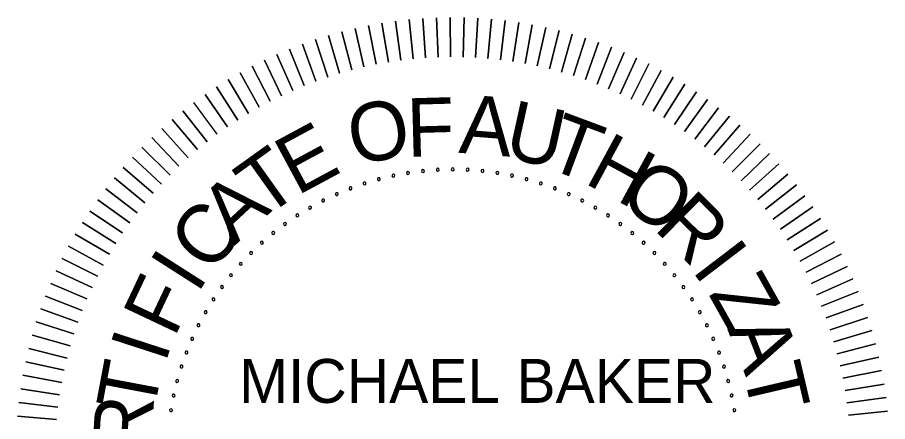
# Model space of a CAD drawing. Extents: x -0.54 to 1.64, y 0 to 0.92.
# Drawn here: x 1.1174 to 1.2012, y 0.1133 to 0.1521 of the extents above; entities that cross this region are included whole.
import ezdxf

# ---------------------------------------------------------------- set-up
doc = ezdxf.new("R2010")
doc.units = 0
doc.layers.add('STAMP_COA', color=7, linetype='Continuous')

msp = doc.modelspace()

# ---------------------------------------------------------------- linework, layer by layer
at = {"layer": 'STAMP_COA'}
for points in [[(1.153107, 0.147847), (1.152493, 0.15159)], [(1.152493, 0.15159), (1.153107, 0.147847)], [(1.154296, 0.148023), (1.1538, 0.151784)], [(1.1538, 0.151784), (1.154296, 0.148023)], [(1.155491, 0.148162), (1.155113, 0.151936)], [(1.155113, 0.151936), (1.155491, 0.148162)], [(1.156688, 0.148263), (1.156429, 0.152047)], [(1.156429, 0.152047), (1.156688, 0.148263)], [(1.157889, 0.148326), (1.157749, 0.152117)], [(1.157749, 0.152117), (1.157889, 0.148326)], [(1.159091, 0.148352), (1.15907, 0.152145)], [(1.15907, 0.152145), (1.159091, 0.148352)], [(1.160293, 0.148339), (1.160391, 0.152131)], [(1.160391, 0.152131), (1.160293, 0.148339)], [(1.161494, 0.14829), (1.161711, 0.152076)], [(1.161711, 0.152076), (1.161494, 0.14829)], [(1.162693, 0.148202), (1.163029, 0.15198)], [(1.163029, 0.15198), (1.162693, 0.148202)], [(1.163888, 0.148077), (1.164343, 0.151842)], [(1.164343, 0.151842), (1.163888, 0.148077)], [(1.16508, 0.147914), (1.165652, 0.151664)], [(1.165652, 0.151664), (1.16508, 0.147914)], [(1.149581, 0.147096), (1.148617, 0.150765)], [(1.148617, 0.150765), (1.149581, 0.147096)], [(1.150748, 0.147384), (1.1499, 0.151081)], [(1.1499, 0.151081), (1.150748, 0.147384)], [(1.151924, 0.147634), (1.151193, 0.151356)], [(1.151193, 0.151356), (1.151924, 0.147634)], [(1.166265, 0.147714), (1.166955, 0.151444)], [(1.166955, 0.151444), (1.166265, 0.147714)], [(1.167443, 0.147477), (1.16825, 0.151183)], [(1.16825, 0.151183), (1.167443, 0.147477)], [(1.168614, 0.147202), (1.169537, 0.150882)], [(1.169537, 0.150882), (1.168614, 0.147202)], [(1.147276, 0.146413), (1.146084, 0.150014)], [(1.146084, 0.150014), (1.147276, 0.146413)], [(1.148423, 0.146773), (1.147345, 0.150409)], [(1.147345, 0.150409), (1.148423, 0.146773)], [(1.169775, 0.146892), (1.170813, 0.15054)], [(1.170813, 0.15054), (1.169775, 0.146892)], [(1.170926, 0.146545), (1.172078, 0.150159)], [(1.172078, 0.150159), (1.170926, 0.146545)], [(1.145019, 0.145586), (1.143603, 0.149105)], [(1.143603, 0.149105), (1.145019, 0.145586)], [(1.146141, 0.146017), (1.144836, 0.149579)], [(1.144836, 0.149579), (1.146141, 0.146017)], [(1.172066, 0.146162), (1.173331, 0.149738)], [(1.173331, 0.149738), (1.172066, 0.146162)], [(1.173192, 0.145743), (1.174569, 0.149277)], [(1.174569, 0.149277), (1.173192, 0.145743)], [(1.143911, 0.14512), (1.142385, 0.148592)], [(1.142385, 0.148592), (1.143911, 0.14512)], [(1.174306, 0.145289), (1.175793, 0.148779)], [(1.175793, 0.148779), (1.174306, 0.145289)], [(1.175404, 0.144801), (1.177, 0.148242)], [(1.177, 0.148242), (1.175404, 0.144801)], [(1.141742, 0.144084), (1.140001, 0.147454)], [(1.140001, 0.147454), (1.141742, 0.144084)], [(1.142818, 0.144619), (1.141184, 0.148042)], [(1.141184, 0.148042), (1.142818, 0.144619)], [(1.176486, 0.144278), (1.17819, 0.147667)], [(1.17819, 0.147667), (1.176486, 0.144278)], [(1.140682, 0.143516), (1.138837, 0.146829)], [(1.138837, 0.146829), (1.140682, 0.143516)], [(1.177552, 0.143721), (1.179361, 0.147055)], [(1.179361, 0.147055), (1.177552, 0.143721)], [(1.139641, 0.142914), (1.137692, 0.146168)], [(1.137692, 0.146168), (1.139641, 0.142914)], [(1.1786, 0.143131), (1.180512, 0.146407)], [(1.180512, 0.146407), (1.1786, 0.143131)], [(1.179628, 0.142509), (1.181643, 0.145723)], [(1.181643, 0.145723), (1.179628, 0.142509)], [(1.13862, 0.14228), (1.13657, 0.145472)], [(1.13657, 0.145472), (1.13862, 0.14228)], [(1.180636, 0.141855), (1.182751, 0.145004)], [(1.182751, 0.145004), (1.180636, 0.141855)], [(1.137619, 0.141615), (1.135469, 0.14474)], [(1.135469, 0.14474), (1.137619, 0.141615)], [(1.181624, 0.141169), (1.183836, 0.14425)], [(1.183836, 0.14425), (1.181624, 0.141169)], [(1.136639, 0.140918), (1.134393, 0.143974)], [(1.182589, 0.140452), (1.184897, 0.143462)], [(1.184897, 0.143462), (1.182589, 0.140452)], [(1.135682, 0.140191), (1.133341, 0.143175)], [(1.133341, 0.143175), (1.135682, 0.140191)], [(1.183531, 0.139706), (1.185933, 0.142642)], [(1.185933, 0.142642), (1.183531, 0.139706)], [(1.134748, 0.139434), (1.132314, 0.142343)], [(1.132314, 0.142343), (1.134748, 0.139434)], [(1.18445, 0.13893), (1.186942, 0.14179)], [(1.186942, 0.14179), (1.18445, 0.13893)], [(1.133838, 0.138648), (1.131314, 0.14148)], [(1.131314, 0.14148), (1.133838, 0.138648)], [(1.187925, 0.140906), (1.185344, 0.138126)], [(1.185344, 0.138126), (1.187925, 0.140906)], [(1.132954, 0.137834), (1.130342, 0.140585)], [(1.130342, 0.140585), (1.132954, 0.137834)], [(1.188879, 0.139992), (1.186211, 0.137295)], [(1.186211, 0.137295), (1.188879, 0.139992)], [(1.132095, 0.136993), (1.129398, 0.13966)], [(1.129398, 0.13966), (1.132095, 0.136993)], [(1.189803, 0.139048), (1.187053, 0.136436)], [(1.187053, 0.136436), (1.189803, 0.139048)], [(1.131263, 0.136125), (1.128484, 0.138706)], [(1.128484, 0.138706), (1.131263, 0.136125)], [(1.130459, 0.135231), (1.1276, 0.137724)], [(1.1276, 0.137724), (1.130459, 0.135231)], [(1.190698, 0.138076), (1.187867, 0.135551)], [(1.187867, 0.135551), (1.190698, 0.138076)], [(1.129684, 0.134313), (1.126748, 0.136714)], [(1.126748, 0.136714), (1.129684, 0.134313)], [(1.191562, 0.137076), (1.188653, 0.134642)], [(1.188653, 0.134642), (1.191562, 0.137076)], [(1.128937, 0.133371), (1.125927, 0.135679)], [(1.125927, 0.135679), (1.128937, 0.133371)], [(1.192394, 0.136049), (1.189409, 0.133708)], [(1.189409, 0.133708), (1.192394, 0.136049)], [(1.193193, 0.134997), (1.190137, 0.13275)], [(1.190137, 0.13275), (1.193193, 0.134997)], [(1.128221, 0.132405), (1.12514, 0.134618)], [(1.12514, 0.134618), (1.128221, 0.132405)], [(1.127535, 0.131418), (1.124386, 0.133532)], [(1.124386, 0.133532), (1.127535, 0.131418)], [(1.193959, 0.13392), (1.190833, 0.131771)], [(1.190833, 0.131771), (1.193959, 0.13392)], [(1.126881, 0.130409), (1.123667, 0.132424)], [(1.123667, 0.132424), (1.126881, 0.130409)], [(1.19469, 0.13282), (1.191499, 0.13077)], [(1.191499, 0.13077), (1.19469, 0.13282)], [(1.195387, 0.131697), (1.192133, 0.129748)], [(1.192133, 0.129748), (1.195387, 0.131697)], [(1.126258, 0.129381), (1.122983, 0.131294)], [(1.122983, 0.131294), (1.126258, 0.129381)], [(1.125668, 0.128334), (1.122334, 0.130142)], [(1.122334, 0.130142), (1.125668, 0.128334)], [(1.196048, 0.130553), (1.192734, 0.128707)], [(1.192734, 0.128707), (1.196048, 0.130553)], [(1.125112, 0.127268), (1.121723, 0.128971)], [(1.121723, 0.128971), (1.125112, 0.127268)], [(1.196673, 0.129389), (1.193303, 0.127648)], [(1.193303, 0.127648), (1.196673, 0.129389)], [(1.19726, 0.128206), (1.193837, 0.126571)], [(1.193837, 0.126571), (1.19726, 0.128206)], [(1.124589, 0.126186), (1.121148, 0.127781)], [(1.121148, 0.127781), (1.124589, 0.126186)], [(1.1241, 0.125087), (1.120611, 0.126574)], [(1.120611, 0.126574), (1.1241, 0.125087)], [(1.197811, 0.127004), (1.194338, 0.125479)], [(1.194338, 0.125479), (1.197811, 0.127004)], [(1.198323, 0.125786), (1.194804, 0.124371)], [(1.194804, 0.124371), (1.198323, 0.125786)], [(1.123647, 0.123974), (1.120112, 0.125351)], [(1.120112, 0.125351), (1.123647, 0.123974)], [(1.123228, 0.122847), (1.119652, 0.124112)], [(1.119652, 0.124112), (1.123228, 0.122847)], [(1.198797, 0.124553), (1.195236, 0.123248)], [(1.195236, 0.123248), (1.198797, 0.124553)], [(1.199232, 0.123305), (1.195631, 0.122113)], [(1.195631, 0.122113), (1.199232, 0.123305)], [(1.122845, 0.121708), (1.119231, 0.12286)], [(1.119231, 0.12286), (1.122845, 0.121708)], [(1.122498, 0.120557), (1.11885, 0.121595)], [(1.11885, 0.121595), (1.122498, 0.120557)], [(1.199628, 0.122045), (1.195991, 0.120966)], [(1.195991, 0.120966), (1.199628, 0.122045)], [(1.199984, 0.120772), (1.196315, 0.119809)], [(1.196315, 0.119809), (1.199984, 0.120772)], [(1.122187, 0.119395), (1.118508, 0.120318)], [(1.118508, 0.120318), (1.122187, 0.119395)], [(1.121913, 0.118225), (1.118207, 0.119032)], [(1.118207, 0.119032), (1.121913, 0.118225)], [(1.200299, 0.119489), (1.196602, 0.118641)], [(1.196602, 0.118641), (1.200299, 0.119489)], [(1.200574, 0.118197), (1.196852, 0.117465)], [(1.196852, 0.117465), (1.200574, 0.118197)], [(1.121676, 0.117046), (1.117946, 0.117736)], [(1.117946, 0.117736), (1.121676, 0.117046)], [(1.121476, 0.115861), (1.117726, 0.116434)], [(1.117726, 0.116434), (1.121476, 0.115861)], [(1.200809, 0.116897), (1.197066, 0.116282)], [(1.197066, 0.116282), (1.200809, 0.116897)], [(1.201002, 0.11559), (1.197242, 0.115093)], [(1.197242, 0.115093), (1.201002, 0.11559)], [(1.121313, 0.11467), (1.117547, 0.115124)], [(1.117547, 0.115124), (1.121313, 0.11467)], [(1.201154, 0.114277), (1.19738, 0.113899)], [(1.19738, 0.113899), (1.201154, 0.114277)], [(1.121188, 0.113474), (1.11741, 0.11381)], [(1.11741, 0.11381), (1.121188, 0.113474)]]:
    msp.add_lwpolyline(points, dxfattribs=at)
for centre, start, end in [((1.156435, 0.137385), 6, 186), ((1.156435, 0.137385), 186, 6), ((1.157867, 0.137498), 3, 183), ((1.157867, 0.137498), 183, 3), ((1.159304, 0.137535), 0, 180), ((1.159304, 0.137535), 180, 0), ((1.160741, 0.137498), 357, 177), ((1.160741, 0.137498), 177, 357), ((1.162173, 0.137385), 174, 354), ((1.162173, 0.137385), 354, 174), ((1.1522, 0.1366), 15, 195), ((1.1522, 0.1366), 195, 15), ((1.153597, 0.136935), 12, 192), ((1.153597, 0.136935), 192, 12), ((1.15501, 0.137197), 9, 189), ((1.15501, 0.137197), 189, 9), ((1.163598, 0.137197), 171, 351), ((1.163598, 0.137197), 351, 171), ((1.165011, 0.136935), 168, 348), ((1.165011, 0.136935), 348, 168), ((1.166409, 0.1366), 165, 345), ((1.166409, 0.1366), 345, 165), ((1.149467, 0.135712), 21, 201), ((1.149467, 0.135712), 201, 21), ((1.150822, 0.136192), 18, 198), ((1.150822, 0.136192), 198, 18), ((1.167786, 0.136192), 162, 342), ((1.167786, 0.136192), 342, 162), ((1.169141, 0.135712), 159, 339), ((1.169141, 0.135712), 339, 159), ((1.148139, 0.135162), 24, 204), ((1.148139, 0.135162), 204, 24), ((1.170469, 0.135162), 156, 336), ((1.170469, 0.135162), 336, 156), ((1.145579, 0.133858), 30, 210), ((1.146842, 0.134543), 27, 207), ((1.146842, 0.134543), 207, 27), ((1.171766, 0.134543), 153, 333), ((1.171766, 0.134543), 333, 153), ((1.173029, 0.133858), 330, 150), ((1.144354, 0.133107), 33, 213), ((1.144354, 0.133107), 213, 33), ((1.145579, 0.133858), 210, 30), ((1.173029, 0.133858), 150, 330), ((1.174254, 0.133107), 147, 327), ((1.174254, 0.133107), 327, 147), ((1.14317, 0.132293), 36, 216), ((1.14317, 0.132293), 216, 36), ((1.175439, 0.132293), 144, 324), ((1.175439, 0.132293), 324, 144), ((1.142029, 0.131418), 39, 219), ((1.142029, 0.131418), 219, 39), ((1.176579, 0.131418), 141, 321), ((1.176579, 0.131418), 321, 141), ((1.140937, 0.130485), 42, 222), ((1.140937, 0.130485), 222, 42), ((1.177671, 0.130485), 138, 318), ((1.177671, 0.130485), 318, 138), ((1.139894, 0.129495), 45, 225), ((1.139894, 0.129495), 225, 45), ((1.178714, 0.129495), 135, 315), ((1.178714, 0.129495), 315, 135), ((1.138905, 0.128453), 48, 228), ((1.138905, 0.128453), 228, 48), ((1.179703, 0.128453), 132, 312), ((1.179703, 0.128453), 312, 132), ((1.137972, 0.12736), 51, 231), ((1.137972, 0.12736), 231, 51), ((1.180636, 0.12736), 129, 309), ((1.180636, 0.12736), 309, 129), ((1.137097, 0.12622), 54, 234), ((1.137097, 0.12622), 234, 54), ((1.181511, 0.12622), 126, 306), ((1.181511, 0.12622), 306, 126), ((1.136283, 0.125036), 57, 237), ((1.136283, 0.125036), 237, 57), ((1.182325, 0.125036), 123, 303), ((1.182325, 0.125036), 303, 123), ((1.135532, 0.12381), 60, 240), ((1.183076, 0.12381), 300, 120), ((1.135532, 0.12381), 240, 60), ((1.183076, 0.12381), 120, 300), ((1.134846, 0.122547), 63, 243), ((1.134846, 0.122547), 243, 63), ((1.183762, 0.122547), 117, 297), ((1.183762, 0.122547), 297, 117), ((1.134227, 0.12125), 66, 246), ((1.134227, 0.12125), 246, 66), ((1.184381, 0.12125), 114, 294), ((1.184381, 0.12125), 294, 114), ((1.133678, 0.119923), 69, 249), ((1.133678, 0.119923), 249, 69), ((1.184931, 0.119923), 111, 291), ((1.184931, 0.119923), 291, 111), ((1.133198, 0.118568), 72, 252), ((1.133198, 0.118568), 252, 72), ((1.18541, 0.118568), 108, 288), ((1.18541, 0.118568), 288, 108), ((1.13279, 0.11719), 75, 255), ((1.13279, 0.11719), 255, 75), ((1.185818, 0.11719), 105, 285), ((1.185818, 0.11719), 285, 105), ((1.132454, 0.115793), 78, 258), ((1.132454, 0.115793), 258, 78), ((1.186154, 0.115793), 102, 282), ((1.186154, 0.115793), 282, 102), ((1.132192, 0.11438), 81, 261), ((1.132192, 0.11438), 261, 81), ((1.186416, 0.11438), 99, 279), ((1.186416, 0.11438), 279, 99)]:
    msp.add_arc(centre, 0.000141, start, end, dxfattribs=at)

# ---------------------------------------------------------------- texts
for s, rotation, p in [('O', 10.72954, (1.149787, 0.137911)), ('F', 1.58665, (1.154933, 0.138724)), ('A', 355.59545, (1.159816, 0.139138)), ('U', 347.54807, (1.164079, 0.138736)), ('T', 339.50069, (1.168013, 0.137796)), ('E', 28.27898, (1.144316, 0.134959)), ('H', 331.45331, (1.171832, 0.13629)), ('T', 35.57245, (1.141172, 0.132778)), ('O', 323.40593, (1.175067, 0.134509)), ('A', 42.86593, (1.138311, 0.130175)), ('R', 315.35854, (1.178558, 0.131838)), ('C', 50.1594, (1.135941, 0.12736)), ('I', 307.31116, (1.18222, 0.12787)), ('I', 57.45288, (1.134717, 0.125476)), ('F', 64.74635, (1.132506, 0.121264)), ('Z', 299.26378, (1.183874, 0.125574)), ('I', 72.03983, (1.131633, 0.118788)), ('A', 291.2164, (1.185721, 0.122186)), ('T', 79.33331, (1.130513, 0.113934)), ('T', 283.16902, (1.187195, 0.1182)), ('R', 86.62678, (1.130255, 0.11021))]:
    msp.add_text(s, height=0.005634, rotation=rotation, dxfattribs=at).set_placement(p)
msp.add_text('MICHAEL BAKER', height=0.00422539, dxfattribs=at).set_placement((1.138745, 0.11508))

doc.saveas('drawing.dxf')
